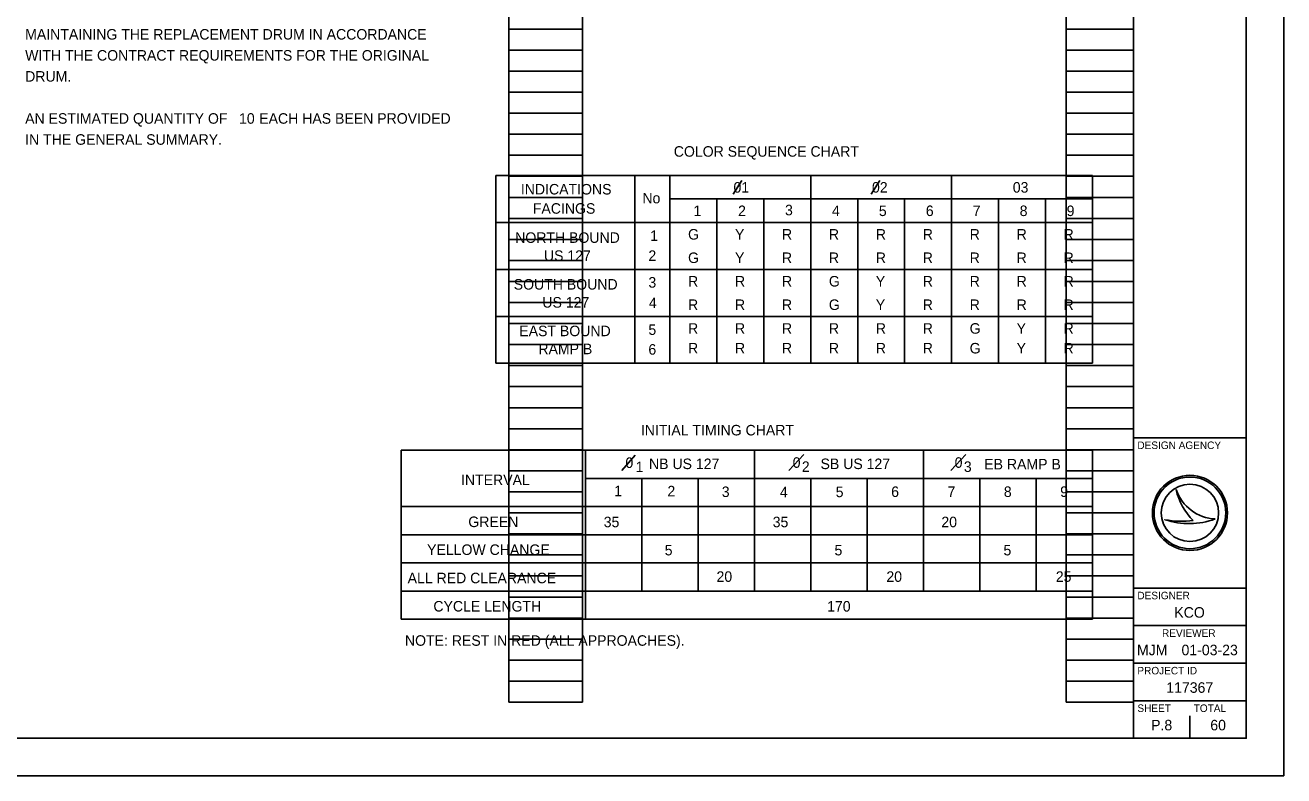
# Model space of a CAD drawing. Extents: x 0 to 34, y 0 to 22.
# Drawn here: x 17.24 to 34, y 0 to 9.99 of the extents above; entities that cross this region are included whole.
import ezdxf

# ---------------------------------------------------------------- set-up
doc = ezdxf.new("R2010")
doc.units = 0
for name, color, linetype in [('Default', 7, 'Continuous'), ('SH_Border', 7, 'Continuous'), ('SH_Cut_Line', 7, 'Continuous'), ('SH_Data', 7, 'Continuous'), ('SH_Text', 7, 'Continuous'), ('TX_P_1', 7, 'Continuous')]:
    doc.layers.add(name, color=color, linetype=linetype)

msp = doc.modelspace()

# ---------------------------------------------------------------- linework, layer by layer
at = {"layer": 'Default'}
for p, q in [((23.507, 7.991), (23.507, 5.491)), ((23.507, 7.991), (31.451, 7.991)), ((25.357, 7.991), (25.357, 5.491)), ((25.826, 7.991), (25.826, 5.491)), ((27.701, 7.991), (27.701, 5.491)), ((29.576, 7.991), (29.576, 6.116)), ((29.576, 7.991), (29.576, 5.491)), ((31.451, 7.991), (31.451, 5.491)), ((25.826, 7.678), (31.451, 7.678)), ((26.451, 7.678), (26.451, 5.491)), ((27.076, 7.678), (27.076, 5.491)), ((28.326, 7.678), (28.326, 5.491)), ((28.951, 7.678), (28.951, 5.491)), ((30.201, 7.678), (30.201, 5.491)), ((30.826, 7.678), (30.826, 5.491)), ((23.507, 7.366), (31.451, 7.366)), ((23.507, 6.741), (31.451, 6.741)), ((23.507, 6.116), (31.451, 6.116)), ((23.507, 6.116), (31.451, 6.116)), ((23.507, 5.491), (31.451, 5.491)), ((22.247, 4.334), (31.451, 4.334)), ((22.247, 4.334), (22.247, 2.084)), ((24.701, 4.334), (24.701, 2.084)), ((26.951, 4.334), (26.951, 2.459)), ((29.201, 4.334), (29.201, 2.459)), ((31.451, 4.334), (31.451, 2.084)), ((24.701, 3.959), (31.451, 3.959)), ((25.451, 3.959), (25.451, 2.459)), ((26.201, 3.959), (26.201, 2.459)), ((27.701, 3.959), (27.701, 2.459)), ((28.451, 3.959), (28.451, 2.459)), ((29.951, 3.959), (29.951, 2.459)), ((30.701, 3.959), (30.701, 2.459)), ((22.247, 3.584), (31.451, 3.584)), ((22.247, 3.209), (31.451, 3.209)), ((22.247, 2.834), (31.451, 2.834)), ((22.247, 2.459), (31.451, 2.459)), ((22.247, 2.084), (31.451, 2.084))]:
    msp.add_line(p, q, dxfattribs=at)
at = {"layer": 'SH_Border'}
for p, q in [((32, 0.5), (32, 21.5)), ((32, 4.5), (33.5, 4.5)), ((32, 2.5), (33.5, 2.5)), ((32, 2), (33.5, 2)), ((32, 1.5), (33.5, 1.5)), ((32, 1), (33.5, 1))]:
    msp.add_line(p, q, dxfattribs=at)
msp.add_lwpolyline([(1.5, 21.5), (33.5, 21.5), (33.5, 0.5), (1.5, 0.5)], close=True, dxfattribs=at)
at = {"layer": 'SH_Cut_Line'}
msp.add_lwpolyline([(0, 0), (34, 0), (34, 22), (0, 22)], close=True, dxfattribs=at)
at = {"layer": 'SH_Data'}
for p, q in [((23.68, 0.98), (23.68, 21.14)), ((24.66, 0.98), (24.66, 21.14)), ((31.1, 0.98), (31.1, 21.14)), ((32, 0.98), (32, 21.14)), ((23.68, 9.94), (24.66, 9.94)), ((31.1, 9.94), (32, 9.94)), ((23.68, 9.66), (24.66, 9.66)), ((31.1, 9.66), (32, 9.66)), ((23.68, 9.38), (24.66, 9.38)), ((31.1, 9.38), (32, 9.38)), ((23.68, 9.1), (24.66, 9.1)), ((31.1, 9.1), (32, 9.1)), ((23.68, 8.82), (24.66, 8.82)), ((31.1, 8.82), (32, 8.82)), ((23.68, 8.54), (24.66, 8.54)), ((31.1, 8.54), (32, 8.54)), ((23.68, 8.26), (24.66, 8.26)), ((31.1, 8.26), (32, 8.26)), ((23.68, 7.98), (24.66, 7.98)), ((31.1, 7.98), (32, 7.98)), ((23.68, 7.7), (24.66, 7.7)), ((31.1, 7.7), (32, 7.7)), ((23.68, 7.42), (24.66, 7.42)), ((31.1, 7.42), (32, 7.42)), ((23.68, 7.14), (24.66, 7.14)), ((31.1, 7.14), (32, 7.14)), ((23.68, 6.86), (24.66, 6.86)), ((31.1, 6.86), (32, 6.86)), ((23.68, 6.58), (24.66, 6.58)), ((31.1, 6.58), (32, 6.58)), ((23.68, 6.3), (24.66, 6.3)), ((31.1, 6.3), (32, 6.3)), ((23.68, 6.02), (24.66, 6.02)), ((31.1, 6.02), (32, 6.02)), ((23.68, 5.74), (24.66, 5.74)), ((31.1, 5.74), (32, 5.74)), ((23.68, 5.46), (24.66, 5.46)), ((31.1, 5.46), (32, 5.46)), ((23.68, 5.18), (24.66, 5.18)), ((31.1, 5.18), (32, 5.18)), ((23.68, 4.9), (24.66, 4.9)), ((31.1, 4.9), (32, 4.9)), ((23.68, 4.62), (24.66, 4.62)), ((31.1, 4.62), (32, 4.62)), ((23.68, 4.34), (24.66, 4.34)), ((31.1, 4.34), (32, 4.34)), ((23.68, 4.06), (24.66, 4.06)), ((31.1, 4.06), (32, 4.06)), ((23.68, 3.78), (24.66, 3.78)), ((31.1, 3.78), (32, 3.78)), ((32.567, 3.81), (32.567, 3.81)), ((23.68, 3.5), (24.66, 3.5)), ((31.1, 3.5), (32, 3.5)), ((32.417, 3.41), (32.417, 3.41)), ((32.75, 3.5), (32.75, 3.5)), ((33.087, 3.419), (33.087, 3.419)), ((23.68, 3.22), (24.66, 3.22)), ((31.1, 3.22), (32, 3.22)), ((23.68, 2.94), (24.66, 2.94)), ((31.1, 2.94), (32, 2.94)), ((23.68, 2.66), (24.66, 2.66)), ((31.1, 2.66), (32, 2.66)), ((23.68, 2.38), (24.66, 2.38)), ((31.1, 2.38), (32, 2.38)), ((23.68, 2.1), (24.66, 2.1)), ((31.1, 2.1), (32, 2.1)), ((23.68, 1.82), (24.66, 1.82)), ((31.1, 1.82), (32, 1.82)), ((23.68, 1.54), (24.66, 1.54)), ((31.1, 1.54), (32, 1.54)), ((23.68, 1.26), (24.66, 1.26)), ((31.1, 1.26), (32, 1.26)), ((23.68, 0.98), (24.66, 0.98)), ((31.1, 0.98), (32, 0.98)), ((32.375, 0.675), (32.375, 0.675)), ((32.75, 0.5), (32.75, 0.8))]:
    msp.add_line(p, q, dxfattribs=at)
for radius in [0.5, 0.477, 0.477, 0.382]:
    msp.add_circle((32.75, 3.5), radius, dxfattribs=at)
for centre, radius, start, end in [((33.116, 3.998), 0.58, 198.9257, 198.9319), ((33.347, 3.97), 0.796, 191.6379, 191.6421), ((33.116, 3.998), 0.58, 198.9319, 267.1657), ((33.347, 3.97), 0.796, 191.6421, 226.0947), ((32.739, 4.37), 1.013, 251.4576, 290.0832), ((32.648, 4.654), 1.266, 259.4964, 259.4995), ((32.739, 4.37), 1.013, 251.4527, 251.4576), ((32.648, 4.654), 1.266, 259.4995, 276.6672)]:
    msp.add_arc(centre, radius, start, end, dxfattribs=at)
at = {"layer": 'TX_P_1'}
for p, q in [((26.667, 7.743), (26.782, 7.924)), ((28.504, 7.743), (28.619, 7.924)), ((25.185, 4.065), (25.361, 4.266)), ((27.409, 4.066), (27.609, 4.275)), ((29.566, 4.066), (29.767, 4.275))]:
    msp.add_line(p, q, dxfattribs=at)

# ---------------------------------------------------------------- texts
at = {"layer": 'Default'}
for s, p in [('COLOR SEQUENCE CHART', (25.877, 8.241)), ('INITIAL TIMING CHART', (25.439, 4.531))]:
    msp.add_text(s, height=0.14, dxfattribs=at).set_placement(p)
at = {"layer": 'SH_Data'}
for s, height, p in [('DESIGN AGENCY', 0.1, (32.05, 4.35)), ('DESIGNER', 0.1, (32.05, 2.35)), ('KCO', 0.14, (32.542, 2.105)), ('REVIEWER', 0.1, (32.378, 1.85)), ('MJM', 0.14, (32.045, 1.605)), ('01-03-23', 0.14, (32.638, 1.605)), ('PROJECT ID', 0.1, (32.05, 1.35)), ('117367', 0.14, (32.435, 1.105)), ('SHEET', 0.1, (32.05, 0.85)), ('TOTAL', 0.1, (32.8, 0.85)), ('P.8', 0.14, (32.233, 0.605)), ('60', 0.14, (33.021, 0.605))]:
    msp.add_text(s, height=height, dxfattribs=at).set_placement(p)
at = {"layer": 'SH_Text'}
for s, p in [('MAINTAINING THE REPLACEMENT DRUM IN ACCORDANCE', (17.24, 9.8)), ('WITH THE CONTRACT REQUIREMENTS FOR THE ORIGINAL', (17.24, 9.52)), ('DRUM.', (17.24, 9.24)), ('AN ESTIMATED QUANTITY OF ', (17.24, 8.68)), ('10', (20.088, 8.68)), (' EACH HAS BEEN PROVIDED', (20.305, 8.68)), ('IN THE GENERAL SUMMARY.', (17.24, 8.4))]:
    msp.add_text(s, height=0.14, dxfattribs=at).set_placement(p)
at = {"layer": 'TX_P_1'}
for s, p in [('INDICATIONS', (23.841, 7.738)), ('01', (26.672, 7.763)), ('02', (28.516, 7.763)), ('03', (30.391, 7.763)), ('No', (25.459, 7.62)), ('FACINGS', (24, 7.482)), ('1', (26.139, 7.451)), ('2', (26.733, 7.451)), ('3', (27.358, 7.461)), ('4', (27.983, 7.451)), ('5', (28.608, 7.451)), ('6', (29.233, 7.451)), ('7', (29.858, 7.451)), ('8', (30.483, 7.451)), ('9', (31.108, 7.451)), ('NORTH BOUND', (23.765, 7.094)), ('1', (25.562, 7.12)), ('G', (26.067, 7.138)), ('Y', (26.692, 7.138)), ('R', (27.317, 7.138)), ('R', (27.942, 7.138)), ('R', (28.567, 7.138)), ('R', (29.192, 7.138)), ('R', (29.817, 7.138)), ('R', (30.442, 7.138)), ('R', (31.067, 7.138)), ('US 127', (24.148, 6.854)), ('2', (25.539, 6.854)), ('G', (26.067, 6.826)), ('Y', (26.692, 6.826)), ('R', (27.317, 6.826)), ('R', (27.942, 6.826)), ('R', (28.567, 6.826)), ('R', (29.192, 6.826)), ('R', (29.817, 6.826)), ('R', (30.442, 6.826)), ('R', (31.067, 6.826)), ('SOUTH BOUND', (23.746, 6.472)), ('3', (25.539, 6.498)), ('R', (26.067, 6.513)), ('R', (26.692, 6.513)), ('R', (27.317, 6.513)), ('G', (27.942, 6.513)), ('Y', (28.567, 6.513)), ('R', (29.192, 6.513)), ('R', (29.817, 6.513)), ('R', (30.442, 6.513)), ('R', (31.067, 6.513)), ('US 127', (24.127, 6.232)), ('4', (25.545, 6.225)), ('R', (26.067, 6.201)), ('R', (26.692, 6.201)), ('R', (27.317, 6.201)), ('G', (27.942, 6.201)), ('Y', (28.567, 6.201)), ('R', (29.192, 6.201)), ('R', (29.817, 6.201)), ('R', (30.442, 6.201)), ('R', (31.067, 6.201)), ('EAST BOUND', (23.82, 5.852)), ('5', (25.539, 5.869)), ('R', (26.067, 5.885)), ('R', (26.692, 5.885)), ('R', (27.317, 5.885)), ('R', (27.942, 5.885)), ('R', (28.567, 5.885)), ('R', (29.192, 5.885)), ('G', (29.817, 5.885)), ('Y', (30.442, 5.885)), ('R', (31.067, 5.885)), ('RAMP B', (24.074, 5.612)), ('6', (25.539, 5.606)), ('R', (26.067, 5.622)), ('R', (26.692, 5.622)), ('R', (27.317, 5.622)), ('R', (27.942, 5.622)), ('R', (28.567, 5.622)), ('R', (29.192, 5.622)), ('G', (29.817, 5.622)), ('Y', (30.442, 5.622)), ('R', (31.067, 5.622)), ('0', (25.233, 4.098)), ('NB US 127', (25.547, 4.083)), ('0', (27.46, 4.1)), ('SB US 127', (27.831, 4.083)), ('0', (29.617, 4.1)), ('EB RAMP B', (30.011, 4.078)), ('1', (25.369, 4.042)), ('2', (27.582, 4.045)), ('3', (29.739, 4.045)), ('INTERVAL ', (23.044, 3.869)), ('1', (25.083, 3.722)), ('2', (25.792, 3.72)), ('3', (26.516, 3.711)), ('4', (27.29, 3.707)), ('5', (28.033, 3.709)), ('6', (28.772, 3.712)), ('7', (29.522, 3.712)), ('8', (30.272, 3.712)), ('9', (31.022, 3.712)), (' GREEN', (23.089, 3.311)), ('35', (24.944, 3.309)), ('35', (27.194, 3.309)), ('20', (29.44, 3.309)), ('YELLOW CHANGE', (22.592, 2.94)), ('5', (25.756, 2.934)), ('5', (28.017, 2.934)), ('5', (30.267, 2.934)), ('ALL RED CLEARANCE', (22.333, 2.563)), ('20', (26.446, 2.582)), ('20', (28.708, 2.582)), ('25', (30.964, 2.582)), ('CYCLE LENGTH', (22.676, 2.187)), ('170', (27.919, 2.186)), ('NOTE: REST IN RED (ALL APPROACHES).', (22.297, 1.731))]:
    msp.add_text(s, height=0.14, dxfattribs=at).set_placement(p)

doc.saveas('drawing.dxf')
